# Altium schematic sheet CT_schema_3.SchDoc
size 300 x 163 mm
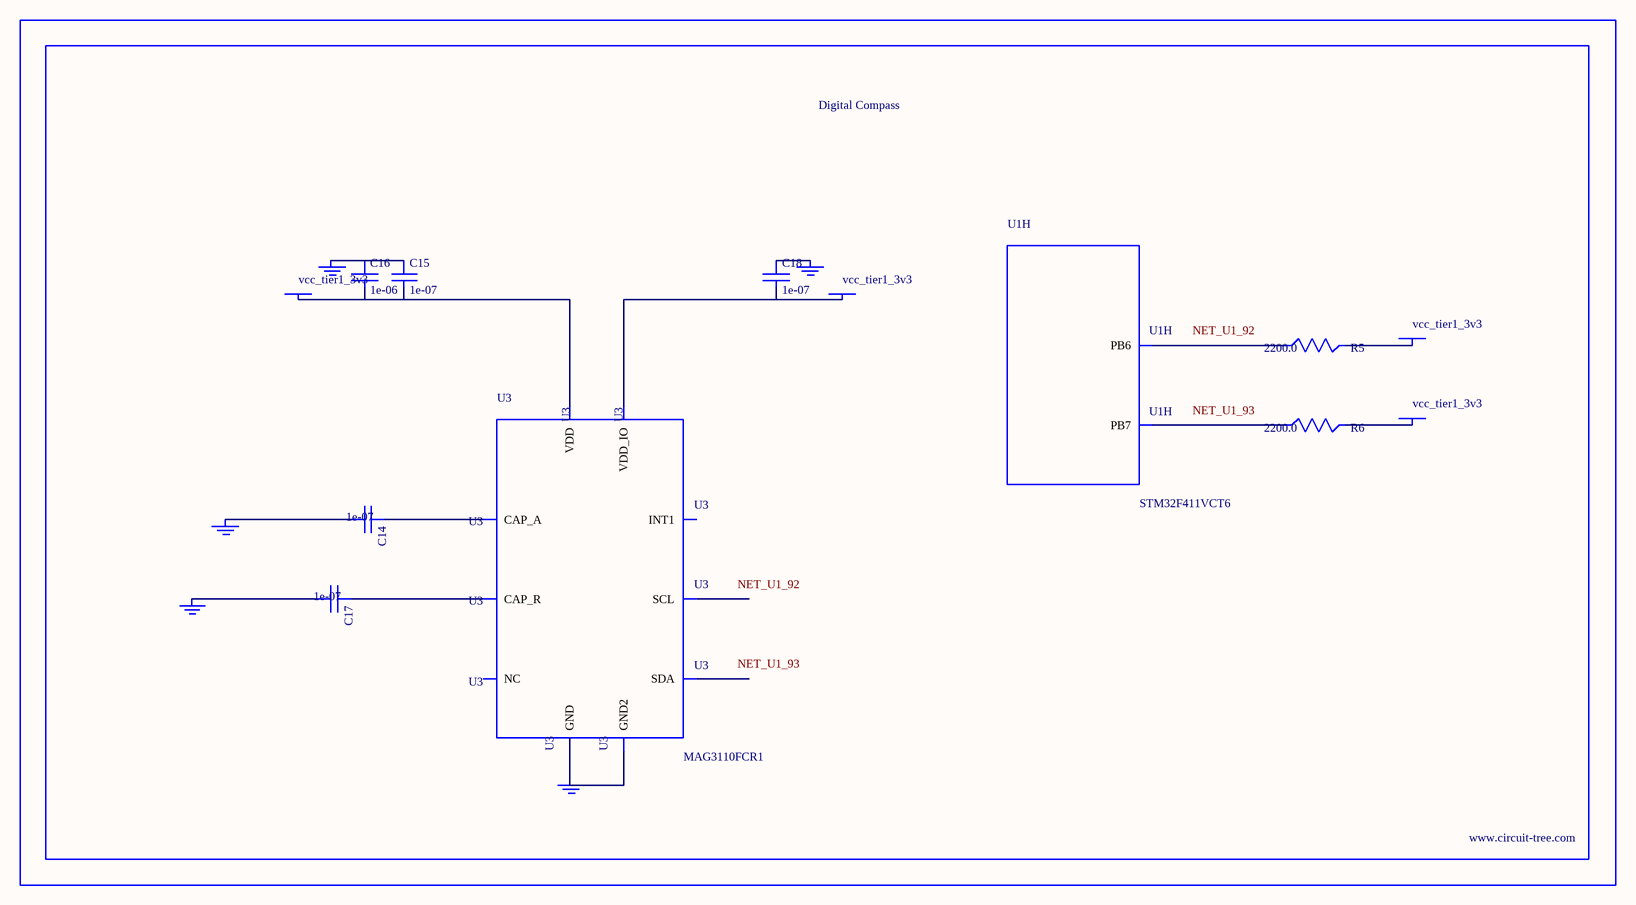
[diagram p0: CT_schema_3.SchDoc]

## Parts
BORDER2  (no value)
C14  1e-07  [C0402]
C15  1e-07  [C0402]
C16  1e-06  [C0603]
C17  1e-07  [C0402]
C18  1e-07  [C0402]
GND_INSTANCE_2_0  (no value)
GND_INSTANCE_2_1  (no value)
GND_INSTANCE_2_2  (no value)
GND_INSTANCE_2_3  (no value)
GND_INSTANCE_2_4  (no value)
POWER_INSTANCE_2_0  vcc_tier1_3v3
POWER_INSTANCE_2_1  vcc_tier1_3v3
POWER_INSTANCE_2_2  vcc_tier1_3v3
POWER_INSTANCE_2_3  vcc_tier1_3v3
R5  2200.0  [R0603]
R6  2200.0  [R0603]
U1  STM32F411VCT6  [LQFP100]  (part H of 9)
U3  MAG3110FCR1  [DFN-10]

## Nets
NetC14_1: C14.1 U3.1(CAP_A)
NetC14_2: C14.2 GND_INSTANCE_2_0.0(GND)
NetC15_1: C15.1 C16.1 GND_INSTANCE_2_1.0(GND)
NetC15_2: C15.2 C16.2 POWER_INSTANCE_2_0.0(PWR) U3.2(VDD)
NetC17_1: C17.1 U3.4(CAP_R)
NetC17_2: C17.2 GND_INSTANCE_2_2.0(GND)
NetC18_1: C18.1 GND_INSTANCE_2_3.0(GND)
NetC18_2: C18.2 POWER_INSTANCE_2_1.0(PWR) U3.8(VDD_IO)
NetGND_INSTANCE_2_4_0: GND_INSTANCE_2_4.0(GND) U3.5(GND) U3.10(GND2)
NetPOWER_INSTANCE_2_2_0: POWER_INSTANCE_2_2.0(PWR) R5.2
NetPOWER_INSTANCE_2_3_0: POWER_INSTANCE_2_3.0(PWR) R6.2
NetR5_1: R5.1 U1.92(PB6)
NetR6_1: R6.1 U1.93(PB7)

Not connected (* = marked no-connect by the designer): U3 3(NC) 6(SDA) 7(SCL) 9(INT1)

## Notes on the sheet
- Labels drawn without touching a wire or pin: NET_U1_92, NET_U1_93

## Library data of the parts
BORDER2 = BORDER_PAGE2
C14 C15 C17 C18 = C0402C104K3RACTU
C16 = C0603C105K3RACTU
GND_INSTANCE_2_0-GND_INSTANCE_2_4 = GND
POWER_INSTANCE_2_0-POWER_INSTANCE_2_3 = PWR
R5 R6 = RC0603JR-072K2L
